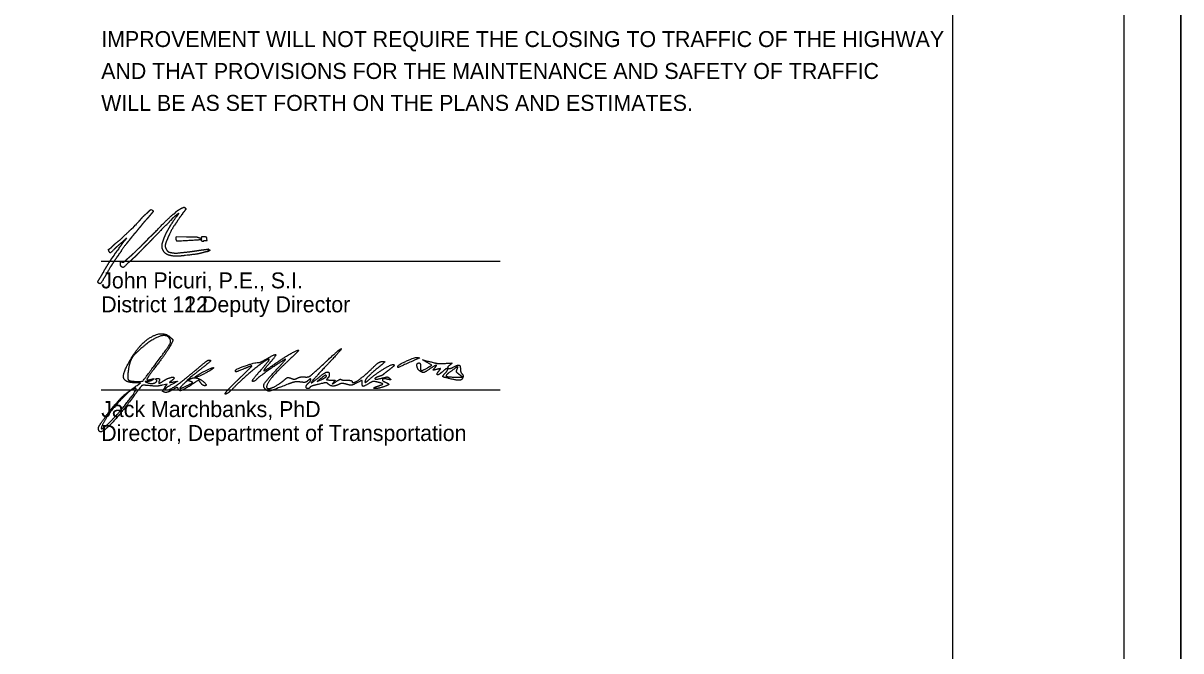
# Model space of a CAD drawing. Extents: x 0 to 44.3, y 0 to 22.
# Drawn here: x 23.84 to 34, y 5.51 to 11.01 of the extents above; entities that cross this region are included whole.
import ezdxf

# ---------------------------------------------------------------- set-up
doc = ezdxf.new("R2010")
doc.units = 0
for name, color, linetype in [('SH_Border', 7, 'Continuous'), ('SH_Cut_Line', 7, 'Continuous'), ('SH_Data', 7, 'Continuous'), ('SH_Text', 7, 'Continuous')]:
    doc.layers.add(name, color=color, linetype=linetype)

msp = doc.modelspace()

# ---------------------------------------------------------------- linework, layer by layer
at = {"layer": 'SH_Border'}
msp.add_line((32, 0.5), (32, 21.5), dxfattribs=at)
msp.add_lwpolyline([(1.5, 21.5), (33.5, 21.5), (33.5, 0.5), (1.5, 0.5)], close=True, dxfattribs=at)
at = {"layer": 'SH_Cut_Line'}
for points in [[(0, 0), (34, 0), (34, 22), (0, 22)], [(0, 22), (34, 22), (34, 0), (0, 0)]]:
    msp.add_lwpolyline(points, close=True, dxfattribs=at)
at = {"layer": 'SH_Data'}
for p, q in [((24.528, 10.875), (24.528, 10.875)), ((24.528, 8.926), (28.028, 8.926)), ((24.528, 7.797), (28.028, 7.797))]:
    msp.add_line(p, q, dxfattribs=at)
at = {"layer": 'SH_Text'}
for p, q in [((25.184, 9.112), (25.184, 9.112)), ((25.407, 9.105), (25.407, 9.105)), ((24.703, 8.88), (24.703, 8.88)), ((24.512, 8.728), (24.512, 8.728)), ((24.99, 8.002), (24.99, 8.002)), ((27.129, 8.001), (27.129, 8.001)), ((25.311, 7.87), (25.311, 7.87)), ((25.356, 7.912), (25.356, 7.912)), ((25.727, 7.883), (25.727, 7.883)), ((26.504, 7.914), (26.504, 7.914)), ((27.582, 7.895), (27.582, 7.895))]:
    msp.add_line(p, q, dxfattribs=at)
for points in [[(24.953, 9.369), (24.964, 9.379), (24.973, 9.374)], [(24.747, 9.121), (24.75, 9.128), (24.744, 9.121)], [(25.277, 9.136), (25.186, 9.137), (25.184, 9.129)], [(25.429, 9.137), (25.407, 9.137), (25.404, 9.124)], [(25.442, 9.107), (25.457, 9.107), (25.456, 9.12)], [(27.393, 7.991), (27.43, 8.013), (27.389, 8.036)], [(27.642, 7.908), (27.698, 7.908), (27.669, 7.93)], [(24.843, 7.835), (24.873, 7.856), (24.835, 7.857)], [(25.085, 7.815), (25.107, 7.847), (25.065, 7.837)], [(26.453, 7.894), (26.423, 7.869), (26.464, 7.888)]]:
    msp.add_lwpolyline(points, dxfattribs=at)
for points in [[(24.911, 9.33), (24.928, 9.345), (24.947, 9.363), (24.953, 9.369)], [(24.976, 9.35), (24.972, 9.346), (24.963, 9.335), (24.956, 9.326)], [(24.973, 9.374), (24.985, 9.367), (24.985, 9.361), (24.976, 9.35)], [(25.21, 9.345), (25.21, 9.347), (25.185, 9.328), (25.162, 9.308)], [(25.17, 9.342), (25.174, 9.344), (25.178, 9.346), (25.178, 9.348)], [(25.178, 9.348), (25.178, 9.354), (25.204, 9.373), (25.23, 9.387)], [(25.193, 9.32), (25.197, 9.324), (25.21, 9.343), (25.21, 9.345)], [(25.23, 9.387), (25.253, 9.399), (25.258, 9.399), (25.268, 9.387)], [(25.252, 9.356), (25.246, 9.35), (25.242, 9.344), (25.242, 9.343)], [(25.261, 9.368), (25.261, 9.367), (25.257, 9.361), (25.252, 9.356)], [(25.267, 9.376), (25.264, 9.373), (25.261, 9.369), (25.261, 9.368)], [(25.268, 9.387), (25.271, 9.383), (25.271, 9.381), (25.267, 9.376)], [(24.824, 9.239), (24.823, 9.24), (24.825, 9.242), (24.829, 9.243)], [(24.829, 9.243), (24.833, 9.244), (24.836, 9.246), (24.836, 9.247)], [(24.836, 9.247), (24.836, 9.249), (24.846, 9.261), (24.858, 9.273)], [(24.858, 9.273), (24.87, 9.286), (24.88, 9.298), (24.88, 9.299)], [(24.885, 9.245), (24.879, 9.237), (24.869, 9.224), (24.863, 9.217)], [(24.88, 9.299), (24.88, 9.3), (24.894, 9.314), (24.911, 9.33)], [(24.938, 9.305), (24.927, 9.293), (24.896, 9.258), (24.885, 9.245)], [(24.956, 9.326), (24.949, 9.318), (24.941, 9.308), (24.938, 9.305)], [(24.999, 9.178), (25.069, 9.252), (25.161, 9.34), (25.17, 9.342)], [(25.13, 9.277), (25.13, 9.274), (25.097, 9.238), (25.094, 9.238)], [(25.119, 9.207), (25.131, 9.23), (25.186, 9.314), (25.193, 9.32)], [(25.133, 9.28), (25.132, 9.28), (25.13, 9.279), (25.13, 9.277)], [(25.146, 9.292), (25.146, 9.288), (25.138, 9.28), (25.133, 9.28)], [(25.162, 9.308), (25.153, 9.3), (25.146, 9.293), (25.146, 9.292)], [(25.2, 9.283), (25.186, 9.261), (25.173, 9.242), (25.172, 9.241)], [(25.238, 9.336), (25.23, 9.327), (25.227, 9.322), (25.2, 9.283)], [(25.242, 9.343), (25.242, 9.341), (25.24, 9.338), (25.238, 9.336)], [(24.678, 9.1), (24.696, 9.114), (24.73, 9.146), (24.771, 9.186)], [(24.771, 9.186), (24.787, 9.202), (24.804, 9.216), (24.807, 9.218)], [(24.802, 9.144), (24.795, 9.135), (24.788, 9.127), (24.788, 9.126)], [(24.818, 9.163), (24.816, 9.161), (24.809, 9.153), (24.802, 9.144)], [(24.807, 9.218), (24.811, 9.219), (24.813, 9.22), (24.812, 9.221)], [(24.812, 9.221), (24.811, 9.222), (24.814, 9.226), (24.818, 9.23)], [(24.818, 9.23), (24.822, 9.234), (24.825, 9.238), (24.824, 9.239)], [(24.837, 9.185), (24.829, 9.175), (24.82, 9.165), (24.818, 9.163)], [(24.863, 9.217), (24.857, 9.21), (24.846, 9.196), (24.837, 9.185)], [(24.958, 9.139), (24.969, 9.149), (24.987, 9.166), (24.999, 9.178)], [(25.094, 9.238), (25.092, 9.238), (25.062, 9.207), (24.992, 9.134)], [(25.074, 9.11), (25.079, 9.127), (25.097, 9.17), (25.104, 9.181)], [(25.104, 9.181), (25.106, 9.183), (25.112, 9.195), (25.119, 9.207)], [(25.172, 9.241), (25.165, 9.235), (25.125, 9.159), (25.112, 9.128)], [(24.598, 9.032), (24.601, 9.033), (24.614, 9.042), (24.625, 9.053)], [(24.625, 9.053), (24.646, 9.074), (24.652, 9.079), (24.678, 9.1)], [(24.685, 9.069), (24.672, 9.057), (24.653, 9.04), (24.643, 9.03)], [(24.744, 9.121), (24.732, 9.109), (24.709, 9.089), (24.685, 9.069)], [(24.685, 9.038), (24.685, 9.04), (24.687, 9.044), (24.689, 9.047)], [(24.689, 9.047), (24.701, 9.059), (24.711, 9.075), (24.709, 9.079)], [(24.751, 9.081), (24.745, 9.074), (24.704, 9.018), (24.704, 9.015)], [(24.709, 9.079), (24.708, 9.081), (24.708, 9.082), (24.71, 9.08)], [(24.71, 9.08), (24.712, 9.079), (24.716, 9.082), (24.719, 9.087)], [(24.719, 9.087), (24.722, 9.092), (24.729, 9.1), (24.734, 9.105)], [(24.734, 9.105), (24.739, 9.111), (24.745, 9.118), (24.747, 9.121)], [(24.771, 9.105), (24.762, 9.094), (24.754, 9.083), (24.751, 9.081)], [(24.788, 9.126), (24.787, 9.125), (24.779, 9.116), (24.771, 9.105)], [(24.812, 8.993), (24.825, 9.005), (24.871, 9.05), (24.897, 9.077)], [(24.912, 9.053), (24.894, 9.034), (24.866, 9.005), (24.849, 8.988)], [(24.897, 9.077), (24.907, 9.087), (24.92, 9.1), (24.926, 9.105)], [(24.992, 9.134), (24.967, 9.108), (24.931, 9.071), (24.912, 9.053)], [(24.926, 9.105), (24.933, 9.111), (24.938, 9.116), (24.938, 9.118)], [(24.938, 9.118), (24.938, 9.12), (24.947, 9.129), (24.958, 9.139)], [(25.068, 9.027), (25.062, 9.039), (25.061, 9.074), (25.066, 9.085)], [(25.066, 9.085), (25.067, 9.089), (25.071, 9.101), (25.074, 9.11)], [(25.104, 9.109), (25.091, 9.081), (25.088, 9.045), (25.097, 9.031)], [(25.112, 9.128), (25.11, 9.121), (25.106, 9.112), (25.104, 9.109)], [(25.184, 9.129), (25.182, 9.124), (25.182, 9.117), (25.184, 9.112)], [(25.184, 9.112), (25.188, 9.102), (25.191, 9.102), (25.284, 9.107)], [(25.371, 9.133), (25.369, 9.135), (25.327, 9.136), (25.277, 9.136)], [(25.284, 9.107), (25.385, 9.112), (25.422, 9.12), (25.388, 9.128)], [(25.388, 9.128), (25.381, 9.13), (25.373, 9.132), (25.371, 9.133)], [(25.404, 9.124), (25.402, 9.112), (25.402, 9.109), (25.407, 9.105)], [(25.407, 9.105), (25.414, 9.1), (25.428, 9.099), (25.428, 9.104)], [(25.428, 9.104), (25.428, 9.106), (25.434, 9.107), (25.442, 9.107)], [(25.452, 9.135), (25.451, 9.136), (25.441, 9.137), (25.429, 9.137)], [(25.456, 9.12), (25.455, 9.127), (25.453, 9.134), (25.452, 9.135)], [(24.597, 9.011), (24.591, 9.023), (24.591, 9.029), (24.598, 9.032)], [(24.643, 9.03), (24.612, 8.999), (24.605, 8.996), (24.597, 9.011)], [(24.608, 8.929), (24.613, 8.936), (24.618, 8.945), (24.621, 8.949)], [(24.621, 8.949), (24.623, 8.953), (24.626, 8.957), (24.628, 8.957)], [(24.628, 8.957), (24.63, 8.957), (24.631, 8.959), (24.631, 8.961)], [(24.631, 8.961), (24.631, 8.964), (24.632, 8.966), (24.634, 8.966)], [(24.634, 8.966), (24.635, 8.966), (24.64, 8.973), (24.645, 8.982)], [(24.673, 8.969), (24.671, 8.969), (24.659, 8.95), (24.644, 8.928)], [(24.645, 8.982), (24.649, 8.99), (24.656, 9.001), (24.661, 9.005)], [(24.661, 9.005), (24.665, 9.01), (24.669, 9.016), (24.67, 9.019)], [(24.67, 9.019), (24.671, 9.021), (24.674, 9.024), (24.676, 9.024)], [(24.679, 8.979), (24.677, 8.975), (24.674, 8.97), (24.673, 8.969)], [(24.676, 9.024), (24.677, 9.024), (24.679, 9.026), (24.679, 9.029)], [(24.679, 9.029), (24.679, 9.031), (24.68, 9.033), (24.682, 9.033)], [(24.686, 8.99), (24.684, 8.988), (24.681, 8.983), (24.679, 8.979)], [(24.682, 9.033), (24.684, 9.033), (24.685, 9.035), (24.685, 9.038)], [(24.704, 9.015), (24.704, 9.013), (24.701, 9.008), (24.686, 8.99)], [(24.744, 8.933), (24.755, 8.943), (24.772, 8.958), (24.783, 8.967)], [(24.81, 8.95), (24.805, 8.946), (24.79, 8.932), (24.777, 8.92)], [(24.783, 8.967), (24.793, 8.976), (24.806, 8.988), (24.812, 8.993)], [(24.849, 8.988), (24.833, 8.971), (24.815, 8.954), (24.81, 8.95)], [(25.13, 8.975), (25.104, 8.982), (25.077, 9.005), (25.068, 9.027)], [(25.097, 9.031), (25.11, 9.011), (25.123, 9.003), (25.156, 8.998)], [(25.256, 8.973), (25.216, 8.968), (25.15, 8.969), (25.13, 8.975)], [(25.156, 8.998), (25.177, 8.995), (25.188, 8.995), (25.244, 9.001)], [(25.244, 9.001), (25.3, 9.007), (25.35, 9.014), (25.381, 9.019)], [(25.428, 9.001), (25.39, 8.991), (25.351, 8.984), (25.256, 8.973)], [(25.381, 9.019), (25.394, 9.021), (25.424, 9.025), (25.434, 9.026)], [(25.459, 9.008), (25.455, 9.008), (25.441, 9.005), (25.428, 9.001)], [(25.434, 9.026), (25.438, 9.026), (25.442, 9.027), (25.442, 9.027)], [(25.442, 9.027), (25.442, 9.027), (25.449, 9.028), (25.458, 9.029)], [(25.458, 9.029), (25.47, 9.03), (25.472, 9.029), (25.466, 9.027)], [(25.466, 9.027), (25.459, 9.025), (25.459, 9.024), (25.47, 9.024)], [(25.47, 9.013), (25.468, 9.01), (25.462, 9.008), (25.459, 9.008)], [(25.47, 9.024), (25.477, 9.024), (25.482, 9.022), (25.482, 9.021)], [(25.479, 9.017), (25.477, 9.017), (25.473, 9.015), (25.47, 9.013)], [(25.482, 9.021), (25.482, 9.019), (25.481, 9.017), (25.479, 9.017)], [(24.551, 8.833), (24.551, 8.835), (24.556, 8.844), (24.561, 8.853)], [(24.561, 8.853), (24.567, 8.862), (24.574, 8.873), (24.576, 8.877)], [(24.576, 8.877), (24.593, 8.906), (24.601, 8.918), (24.608, 8.929)], [(24.615, 8.884), (24.613, 8.881), (24.608, 8.874), (24.587, 8.836)], [(24.644, 8.928), (24.63, 8.906), (24.617, 8.886), (24.615, 8.884)], [(24.703, 8.88), (24.699, 8.884), (24.697, 8.891), (24.698, 8.899)], [(24.698, 8.899), (24.698, 8.917), (24.7, 8.919), (24.714, 8.917)], [(24.777, 8.92), (24.729, 8.874), (24.715, 8.866), (24.703, 8.88)], [(24.714, 8.917), (24.724, 8.915), (24.727, 8.917), (24.744, 8.933)], [(24.502, 8.737), (24.497, 8.744), (24.498, 8.746), (24.511, 8.767)], [(24.512, 8.728), (24.509, 8.729), (24.504, 8.733), (24.502, 8.737)], [(24.511, 8.767), (24.519, 8.779), (24.53, 8.797), (24.536, 8.808)], [(24.544, 8.763), (24.544, 8.759), (24.521, 8.726), (24.519, 8.727)], [(24.536, 8.808), (24.541, 8.818), (24.547, 8.827), (24.548, 8.828)], [(24.554, 8.779), (24.549, 8.772), (24.544, 8.764), (24.544, 8.763)], [(24.548, 8.828), (24.55, 8.829), (24.551, 8.831), (24.551, 8.833)], [(24.564, 8.795), (24.564, 8.794), (24.559, 8.787), (24.554, 8.779)], [(24.571, 8.809), (24.567, 8.802), (24.564, 8.796), (24.564, 8.795)], [(24.587, 8.836), (24.582, 8.827), (24.575, 8.815), (24.571, 8.809)], [(24.519, 8.727), (24.518, 8.727), (24.515, 8.728), (24.512, 8.728)], [(24.779, 8.053), (24.865, 8.203), (25.073, 8.319), (25.139, 8.253)], [(25.13, 8.244), (25.104, 8.286), (24.978, 8.245), (24.883, 8.163)], [(24.99, 8.002), (25.112, 8.165), (25.144, 8.222), (25.13, 8.244)], [(25.139, 8.253), (25.158, 8.235), (25.158, 8.23), (25.139, 8.191)], [(24.883, 8.163), (24.816, 8.106), (24.777, 8.042), (24.766, 7.971)], [(25.139, 8.191), (25.128, 8.168), (25.077, 8.093), (25.024, 8.023)], [(26.033, 8.011), (26.113, 8.068), (26.244, 8.145), (26.26, 8.145)], [(26.26, 8.145), (26.265, 8.145), (26.224, 8.102), (26.168, 8.05)], [(26.487, 8.031), (26.562, 8.101), (26.628, 8.157), (26.634, 8.157)], [(26.634, 8.157), (26.639, 8.157), (26.587, 8.097), (26.518, 8.024)], [(24.835, 7.857), (24.737, 7.858), (24.714, 7.94), (24.779, 8.053)], [(25.369, 7.979), (25.419, 8.022), (25.465, 8.057), (25.47, 8.057)], [(25.47, 8.057), (25.495, 8.058), (25.472, 8.032), (25.386, 7.965)], [(26.002, 8.064), (25.992, 8.074), (25.782, 7.907), (25.704, 7.828)], [(25.705, 7.967), (25.705, 7.977), (25.892, 8.041), (25.908, 8.035)], [(26.142, 8.064), (26.093, 8.036), (25.905, 7.904), (25.891, 7.888)], [(25.908, 8.035), (25.914, 8.034), (25.943, 8.047), (25.974, 8.065)], [(25.924, 7.964), (25.97, 8.016), (26.005, 8.061), (26.002, 8.064)], [(26.005, 8.03), (25.977, 7.998), (25.954, 7.969), (25.954, 7.964)], [(25.974, 8.065), (26.052, 8.111), (26.065, 8.098), (26.005, 8.03)], [(26.168, 8.05), (26.069, 7.957), (25.979, 7.848), (25.979, 7.821)], [(26.077, 7.985), (26.123, 8.034), (26.152, 8.07), (26.142, 8.064)], [(26.312, 7.909), (26.345, 7.906), (26.369, 7.923), (26.487, 8.031)], [(26.895, 7.975), (26.94, 8.019), (26.977, 8.045), (26.995, 8.044)], [(26.995, 8.044), (27.019, 8.044), (27.016, 8.038), (26.967, 7.998)], [(27.129, 8.001), (27.129, 8.013), (27.282, 8.084), (27.301, 8.08)], [(27.301, 8.08), (27.322, 8.076), (27.323, 8.076), (27.201, 8.022)], [(27.33, 7.957), (27.304, 7.971), (27.293, 8.032), (27.317, 8.032)], [(27.317, 8.032), (27.324, 8.032), (27.329, 8.018), (27.329, 8.001)], [(27.389, 8.036), (27.346, 8.06), (27.345, 8.06), (27.448, 8.034)], [(27.448, 8.034), (27.469, 8.028), (27.514, 8.026), (27.548, 8.028)], [(27.548, 8.028), (27.603, 8.031), (27.608, 8.029), (27.588, 8.014)], [(24.766, 7.971), (24.755, 7.898), (24.776, 7.87), (24.844, 7.87)], [(24.844, 7.87), (24.891, 7.87), (24.895, 7.874), (24.99, 8.002)], [(25.024, 8.023), (24.972, 7.954), (24.929, 7.893), (24.929, 7.888)], [(25.108, 7.795), (25.131, 7.795), (25.257, 7.884), (25.369, 7.979)], [(25.386, 7.965), (25.293, 7.892), (25.271, 7.87), (25.315, 7.894)], [(25.356, 7.912), (25.376, 7.93), (25.508, 7.996), (25.513, 7.99)], [(25.513, 7.99), (25.519, 7.984), (25.377, 7.907), (25.359, 7.907)], [(25.786, 7.982), (25.723, 7.956), (25.704, 7.952), (25.705, 7.967)], [(25.727, 7.883), (25.798, 7.951), (25.854, 8.007), (25.85, 8.007)], [(25.85, 8.007), (25.847, 8.007), (25.818, 7.996), (25.786, 7.982)], [(25.858, 7.87), (25.848, 7.87), (25.877, 7.911), (25.924, 7.964)], [(25.954, 7.964), (25.954, 7.96), (25.99, 7.981), (26.033, 8.011)], [(25.97, 7.799), (25.945, 7.825), (25.973, 7.875), (26.077, 7.985)], [(26.518, 8.024), (26.388, 7.886), (26.356, 7.839), (26.439, 7.907)], [(26.439, 7.907), (26.487, 7.946), (26.529, 7.957), (26.529, 7.929)], [(26.504, 7.914), (26.504, 7.927), (26.48, 7.918), (26.453, 7.894)], [(26.529, 7.929), (26.529, 7.92), (26.523, 7.906), (26.514, 7.897)], [(26.729, 7.868), (26.729, 7.846), (26.825, 7.907), (26.895, 7.975)], [(26.967, 7.998), (26.893, 7.937), (26.842, 7.883), (26.842, 7.866)], [(26.876, 7.884), (26.93, 7.933), (27.077, 8.023), (27.094, 8.017)], [(27.004, 7.931), (27.001, 7.927), (26.986, 7.919), (26.97, 7.915)], [(27.06, 7.976), (27.033, 7.955), (27.008, 7.935), (27.004, 7.931)], [(27.094, 8.017), (27.102, 8.014), (27.087, 7.996), (27.06, 7.976)], [(27.201, 8.022), (27.138, 7.994), (27.129, 7.991), (27.129, 8.001)], [(27.329, 8.001), (27.329, 7.964), (27.344, 7.962), (27.393, 7.991)], [(27.405, 7.975), (27.365, 7.949), (27.352, 7.945), (27.33, 7.957)], [(27.453, 7.987), (27.477, 8.016), (27.461, 8.012), (27.405, 7.975)], [(27.472, 7.975), (27.439, 7.967), (27.437, 7.968), (27.453, 7.987)], [(27.492, 7.964), (27.507, 7.982), (27.505, 7.983), (27.472, 7.975)], [(27.521, 7.955), (27.489, 7.925), (27.466, 7.932), (27.492, 7.964)], [(27.546, 7.943), (27.577, 7.976), (27.555, 7.987), (27.521, 7.955)], [(27.582, 7.895), (27.527, 7.908), (27.522, 7.915), (27.546, 7.943)], [(27.589, 7.953), (27.546, 7.922), (27.563, 7.908), (27.642, 7.908)], [(27.588, 8.014), (27.559, 7.993), (27.582, 7.976), (27.616, 7.994)], [(27.65, 7.976), (27.66, 8.001), (27.651, 7.998), (27.589, 7.953)], [(27.616, 7.994), (27.656, 8.016), (27.679, 8.01), (27.679, 7.979)], [(27.669, 7.93), (27.649, 7.946), (27.643, 7.959), (27.65, 7.976)], [(27.679, 7.979), (27.679, 7.963), (27.686, 7.944), (27.694, 7.936)], [(27.694, 7.936), (27.701, 7.928), (27.704, 7.913), (27.7, 7.902)], [(24.592, 7.593), (24.669, 7.693), (24.749, 7.77), (24.843, 7.835)], [(24.924, 7.835), (24.89, 7.838), (24.879, 7.828), (24.802, 7.726)], [(24.936, 7.869), (24.913, 7.868), (24.914, 7.867), (24.94, 7.857)], [(25.065, 7.837), (25.025, 7.828), (25.002, 7.827), (24.924, 7.835)], [(24.929, 7.888), (24.929, 7.884), (24.945, 7.883), (24.964, 7.888)], [(24.979, 7.883), (24.969, 7.876), (24.949, 7.87), (24.936, 7.869)], [(24.94, 7.857), (24.97, 7.845), (25.026, 7.869), (25.009, 7.887)], [(24.964, 7.888), (24.989, 7.894), (24.993, 7.892), (24.979, 7.883)], [(25.009, 7.887), (25.004, 7.891), (25.01, 7.895), (25.022, 7.895)], [(25.022, 7.895), (25.037, 7.895), (25.042, 7.889), (25.037, 7.876)], [(25.037, 7.876), (25.029, 7.853), (25.041, 7.852), (25.074, 7.874)], [(25.074, 7.874), (25.102, 7.894), (25.167, 7.912), (25.167, 7.9)], [(25.152, 7.846), (25.101, 7.817), (25.081, 7.795), (25.108, 7.795)], [(25.145, 7.876), (25.126, 7.862), (25.128, 7.861), (25.161, 7.865)], [(25.167, 7.9), (25.167, 7.895), (25.157, 7.884), (25.145, 7.876)], [(25.161, 7.865), (25.198, 7.871), (25.198, 7.871), (25.152, 7.846)], [(25.316, 7.838), (25.248, 7.794), (25.21, 7.784), (25.202, 7.809)], [(25.258, 7.854), (25.213, 7.813), (25.225, 7.804), (25.283, 7.834)], [(25.311, 7.87), (25.293, 7.877), (25.277, 7.872), (25.258, 7.854)], [(25.283, 7.834), (25.329, 7.858), (25.333, 7.862), (25.311, 7.87)], [(25.315, 7.894), (25.328, 7.901), (25.351, 7.903), (25.368, 7.899)], [(25.401, 7.857), (25.384, 7.881), (25.382, 7.881), (25.316, 7.838)], [(25.359, 7.907), (25.354, 7.907), (25.353, 7.909), (25.356, 7.912)], [(25.368, 7.899), (25.404, 7.889), (25.463, 7.832), (25.436, 7.832)], [(25.436, 7.832), (25.426, 7.832), (25.411, 7.844), (25.401, 7.857)], [(25.617, 7.758), (25.607, 7.758), (25.656, 7.815), (25.727, 7.883)], [(25.704, 7.828), (25.667, 7.789), (25.627, 7.758), (25.617, 7.758)], [(25.891, 7.888), (25.883, 7.878), (25.868, 7.87), (25.858, 7.87)], [(26.169, 7.847), (26.023, 7.789), (25.988, 7.781), (25.97, 7.799)], [(25.979, 7.821), (25.979, 7.814), (25.988, 7.807), (25.998, 7.807)], [(25.998, 7.807), (26.019, 7.807), (26.101, 7.853), (26.137, 7.885)], [(26.137, 7.885), (26.157, 7.903), (26.17, 7.906), (26.194, 7.897)], [(26.275, 7.864), (26.246, 7.868), (26.206, 7.861), (26.169, 7.847)], [(26.194, 7.897), (26.214, 7.889), (26.233, 7.89), (26.249, 7.899)], [(26.249, 7.899), (26.262, 7.906), (26.291, 7.911), (26.312, 7.909)], [(26.344, 7.878), (26.329, 7.864), (26.307, 7.86), (26.275, 7.864)], [(26.341, 7.807), (26.323, 7.807), (26.327, 7.84), (26.348, 7.857)], [(26.367, 7.886), (26.367, 7.893), (26.357, 7.89), (26.344, 7.878)], [(26.348, 7.857), (26.359, 7.866), (26.367, 7.879), (26.367, 7.886)], [(26.436, 7.845), (26.397, 7.836), (26.363, 7.824), (26.359, 7.818)], [(26.52, 7.847), (26.509, 7.858), (26.489, 7.858), (26.436, 7.845)], [(26.464, 7.888), (26.486, 7.899), (26.504, 7.911), (26.504, 7.914)], [(26.514, 7.897), (26.503, 7.886), (26.509, 7.882), (26.541, 7.882)], [(26.616, 7.845), (26.585, 7.828), (26.538, 7.829), (26.52, 7.847)], [(26.541, 7.882), (26.579, 7.882), (26.581, 7.88), (26.565, 7.861)], [(26.565, 7.861), (26.553, 7.846), (26.56, 7.848), (26.587, 7.867)], [(26.587, 7.867), (26.609, 7.882), (26.629, 7.891), (26.633, 7.887)], [(26.681, 7.845), (26.654, 7.852), (26.631, 7.852), (26.616, 7.845)], [(26.633, 7.887), (26.637, 7.883), (26.66, 7.88), (26.685, 7.88)], [(26.77, 7.856), (26.732, 7.837), (26.714, 7.835), (26.681, 7.845)], [(26.685, 7.88), (26.709, 7.88), (26.729, 7.875), (26.729, 7.868)], [(26.817, 7.856), (26.817, 7.879), (26.816, 7.879), (26.77, 7.856)], [(26.879, 7.853), (26.834, 7.826), (26.817, 7.827), (26.817, 7.856)], [(26.842, 7.866), (26.842, 7.859), (26.857, 7.867), (26.876, 7.884)], [(26.962, 7.861), (26.923, 7.871), (26.906, 7.869), (26.879, 7.853)], [(26.998, 7.82), (26.952, 7.805), (26.904, 7.81), (26.948, 7.826)], [(26.97, 7.915), (26.921, 7.899), (26.94, 7.885), (26.992, 7.899)], [(26.948, 7.826), (26.962, 7.831), (26.982, 7.838), (26.992, 7.842)], [(26.992, 7.842), (27.003, 7.846), (26.992, 7.853), (26.962, 7.861)], [(26.992, 7.899), (27.03, 7.909), (27.045, 7.909), (27.058, 7.897)], [(27.039, 7.889), (27.002, 7.898), (26.989, 7.875), (27.023, 7.862)], [(27.023, 7.862), (27.054, 7.85), (27.045, 7.835), (26.998, 7.82)], [(27.058, 7.897), (27.07, 7.884), (27.067, 7.882), (27.039, 7.889)], [(27.7, 7.902), (27.692, 7.881), (27.651, 7.878), (27.582, 7.895)], [(24.802, 7.726), (24.65, 7.524), (24.504, 7.395), (24.504, 7.462)], [(24.835, 7.806), (24.814, 7.827), (24.596, 7.601), (24.55, 7.511)], [(24.62, 7.529), (24.687, 7.598), (24.843, 7.798), (24.835, 7.806)], [(25.084, 7.775), (25.066, 7.782), (25.066, 7.786), (25.085, 7.815)], [(25.151, 7.795), (25.125, 7.78), (25.095, 7.771), (25.084, 7.775)], [(25.202, 7.809), (25.199, 7.817), (25.18, 7.812), (25.151, 7.795)], [(26.359, 7.818), (26.356, 7.812), (26.348, 7.807), (26.341, 7.807)], [(24.504, 7.462), (24.504, 7.472), (24.544, 7.531), (24.592, 7.593)], [(24.55, 7.511), (24.518, 7.45), (24.55, 7.458), (24.62, 7.529)]]:
    msp.add_open_spline(points, degree=2, dxfattribs=at)

# ---------------------------------------------------------------- texts
at = {"layer": 'SH_Data'}
for s, p in [('IMPROVEMENT WILL NOT REQUIRE THE CLOSING TO TRAFFIC OF THE HIGHWAY', (24.528, 10.803)), ('AND THAT PROVISIONS FOR THE MAINTENANCE AND SAFETY OF TRAFFIC', (24.528, 10.523)), ('WILL BE AS SET FORTH ON THE PLANS AND ESTIMATES.', (24.528, 10.243))]:
    msp.add_text(s, height=0.14, dxfattribs=at).set_placement(p)
at = {"layer": 'SH_Text'}
for s, p in [('John Picuri, P.E.', (24.528, 8.686)), ('John Picuri, P.E., S.I.', (24.528, 8.686)), ('District 12 Deputy Director', (24.528, 8.476)), ('              12', (24.528, 8.476)), ('Jack Marchbanks, PhD', (24.528, 7.557)), ('Director, Department of Transportation', (24.528, 7.347))]:
    msp.add_text(s, height=0.14, dxfattribs=at).set_placement(p)

doc.saveas('drawing.dxf')
